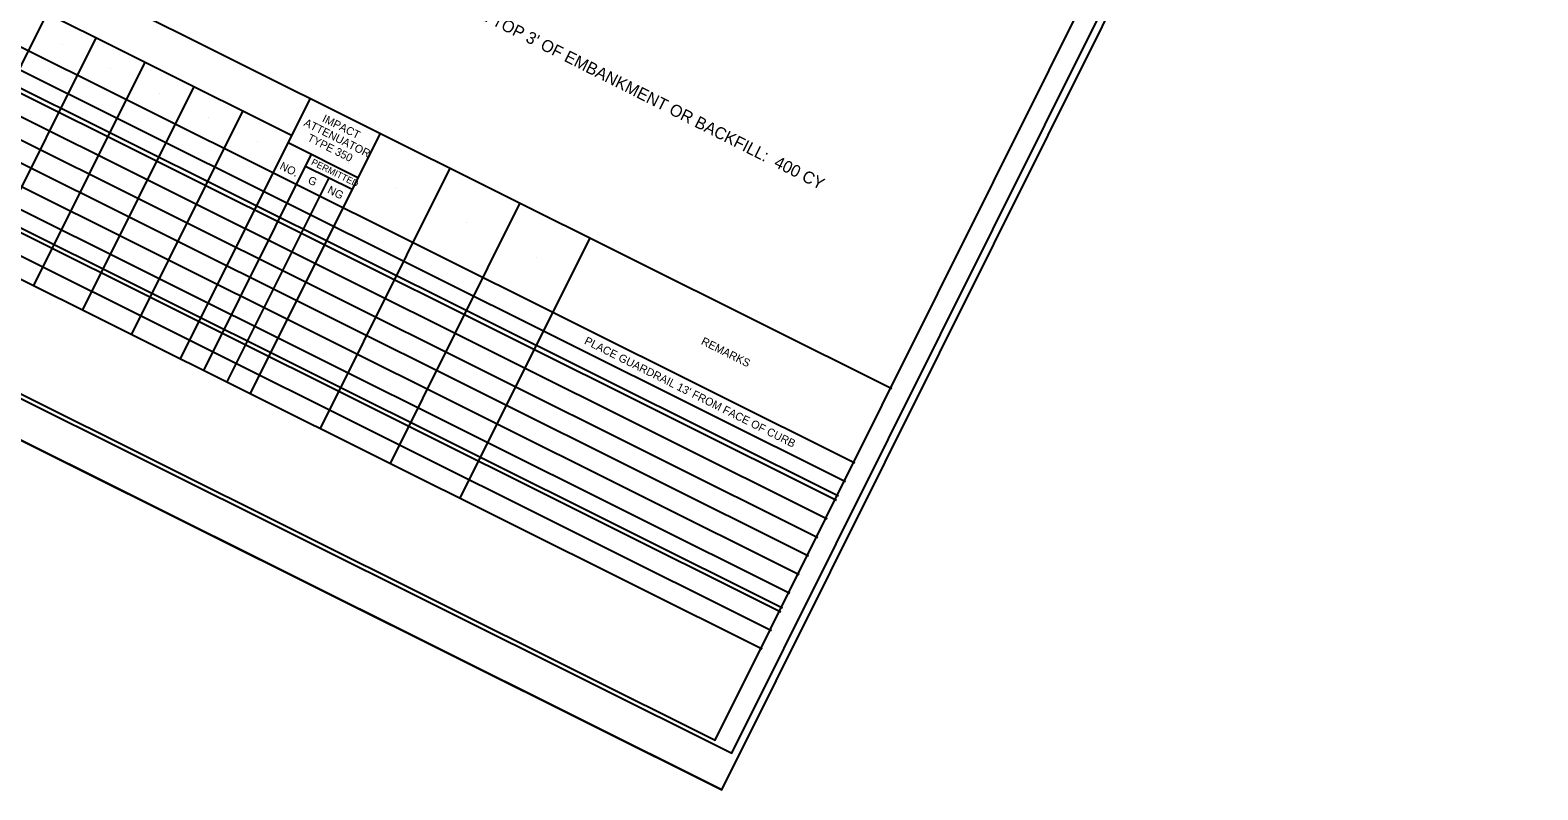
# Model space of a CAD drawing. Extents: x 1771109 to 1774678, y 884436 to 887277.
# Drawn here: x 1773772 to 1774678, y 885541 to 885998 of the extents above; entities that cross this region are included whole.
import ezdxf

# ---------------------------------------------------------------- set-up
doc = ezdxf.new("R2010")
doc.units = 0
for name, color, linetype in [('Sheet Border Standard 30in CELL', 7, 'Continuous'), ('Sheet Cutting Line CELL', 7, 'Continuous'), ('Sheet Plot Border Inside CELL', 7, 'Continuous'), ('Sheet Plot Border Outside CELL', 7, 'Continuous'), ('Sheet Summary Combination CELL', 7, 'Continuous'), ('Sheet Summary Guardrail CELL', 7, 'Continuous')]:
    doc.layers.add(name, color=color, linetype=linetype)

msp = doc.modelspace()

# ---------------------------------------------------------------- linework, layer by layer
at = {"layer": 'Sheet Border Standard 30in CELL'}
msp.add_lwpolyline([(1774652.12, 886510.92), (1773309.73, 887180.24), (1772841.21, 886240.56), (1774183.6, 885571.25)], close=True, dxfattribs=at)
at = {"layer": 'Sheet Cutting Line CELL'}
for p, q in [((1774187.66, 885541.29), (1772680.6, 886292.7)), ((1772680.6, 886292.7), (1774187.66, 885541.29))]:
    msp.add_line(p, q, dxfattribs=at)
at = {"layer": 'Sheet Plot Border Inside CELL'}
msp.add_lwpolyline([(1774664.45, 886507.63), (1773173.05, 887251.23), (1772702.25, 886307), (1774193.65, 885563.39)], close=True, dxfattribs=at)
at = {"layer": 'Sheet Plot Border Outside CELL'}
msp.add_lwpolyline([(1774678.49, 886525.71), (1773171.43, 887277.13), (1772680.6, 886292.7), (1774187.66, 885541.29)], close=True, dxfattribs=at)
at = {"layer": 'Sheet Summary Guardrail CELL'}
for p, q in [((1772947.61, 886451.91), (1774290, 885782.59)), ((1772925.3, 886407.16), (1774267.69, 885737.85)), ((1772919.72, 886395.97), (1774262.11, 885726.66)), ((1772914.14, 886384.79), (1774256.53, 885715.47)), ((1772915.4, 886387.32), (1774257.8, 885718)), ((1772908.56, 886373.6), (1774250.96, 885704.29)), ((1772902.99, 886362.41), (1774245.38, 885693.1)), ((1772897.41, 886351.23), (1774239.8, 885681.91)), ((1772891.83, 886340.04), (1774234.22, 885670.73)), ((1772886.25, 886328.85), (1774228.65, 885659.54)), ((1772880.68, 886317.67), (1774223.07, 885648.35)), ((1772881.83, 886319.99), (1774224.23, 885650.68)), ((1772875.1, 886306.48), (1774217.49, 885637.17)), ((1772869.52, 886295.29), (1774211.91, 885625.98)), ((1773928.84, 885934.73), (1773500.7, 886148.2)), ((1773781.62, 886008.13), (1773714.69, 885873.89)), ((1773811.07, 885993.45), (1773744.13, 885859.21)), ((1773790.77, 885989.61), (1773790.77, 885989.61)), ((1773840.51, 885978.77), (1773773.58, 885844.53)), ((1773820.21, 885974.93), (1773820.21, 885974.93)), ((1773869.95, 885964.09), (1773803.02, 885829.85)), ((1773849.65, 885960.25), (1773849.65, 885960.25)), ((1773899.39, 885949.41), (1773832.46, 885815.17)), ((1773939.99, 885957.1), (1773861.91, 885800.49)), ((1773879.1, 885945.57), (1773879.1, 885945.57)), ((1773982.05, 885936.13), (1773903.97, 885779.52)), ((1773908.54, 885930.88), (1773908.54, 885930.88)), ((1773926.72, 885930.48), (1773968.78, 885909.51)), ((1773940.72, 885923.5), (1773875.91, 885793.51)), ((1773937.15, 885916.34), (1773965.21, 885902.35)), ((1774024.12, 885915.16), (1773946.03, 885758.55)), ((1773963.05, 885917.95), (1773963.05, 885917.95)), ((1773951.16, 885909.35), (1773889.92, 885786.53)), ((1773991.93, 885903.27), (1773991.93, 885903.27)), ((1774066.18, 885894.19), (1773988.09, 885737.58)), ((1774033.99, 885882.3), (1774033.99, 885882.3)), ((1774108.24, 885873.22), (1774030.15, 885716.6)), ((1774076.05, 885861.33), (1774076.05, 885861.33))]:
    msp.add_line(p, q, dxfattribs=at)

# ---------------------------------------------------------------- texts
at = {"layer": 'Sheet Summary Combination CELL'}
msp.add_text("UNCLASSIFIED EXCAVATION- ACCEPTABLE, BUT NOT TO BE PLACED IN THE TOP 3' OF EMBANKMENT OR BACKFILL:  400 CY", height=7.2, rotation=333.30813, dxfattribs=at).set_placement((1773725.9, 886163.89))
at = {"layer": 'Sheet Summary Guardrail CELL'}
for s, height, p in [('ATTENUATOR', 4.8, (1773935.78, 885940.78)), ('IMPACT', 4.8, (1773946.87, 885943.3)), ('TYPE 350', 4.8, (1773937.89, 885931.68)), ('NO.', 4.8, (1773921.27, 885914.79)), ('PERMITTED', 4, (1773940.27, 885917.35)), ('G', 4.8, (1773938.19, 885906.32)), ('NG', 4.8, (1773950.01, 885900.43)), ("PLACE GUARDRAIL 13' FROM FACE OF CURB", 4.8, (1774104.54, 885809.69)), ('REMARKS', 4.8, (1774174.81, 885809.41))]:
    msp.add_text(s, height=height, rotation=333.49928, dxfattribs=at).set_placement(p)

doc.saveas('drawing.dxf')
